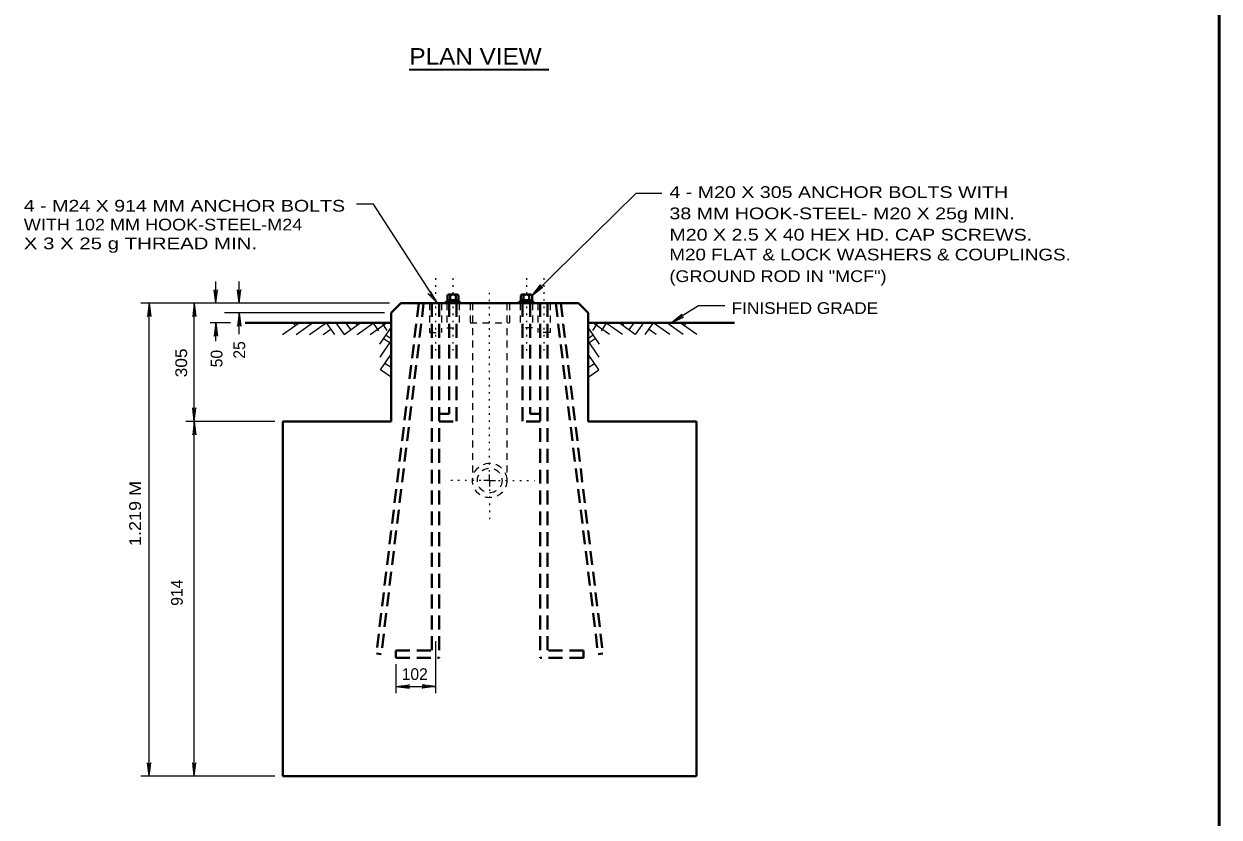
# Model space of a CAD drawing. Extents: x 312583 to 312854, y 144419 to 144597.
# Drawn here: x 312633.1 to 312710.6, y 144490.1 to 144541.5 of the extents above; entities that cross this region are included whole.
import ezdxf
from ezdxf.enums import TextEntityAlignment as Align

# ---------------------------------------------------------------- set-up
doc = ezdxf.new("R2010")
doc.units = 0
doc.header["$LTSCALE"] = 0.3
for name, pattern in [('DOTTED', [1.5, 0.3, -1.2]), ('MEDIUM_DASHED', [4.5, 3, -1.5]), ('SHORT_DASHED', [2.7, 1.5, -1.2])]:
    doc.linetypes.add(name, pattern=pattern)
doc.layers.add('1', color=7, linetype='Continuous', lineweight=40)
doc.layers.add('2', color=7, linetype='Continuous', lineweight=13)

msp = doc.modelspace()

# ---------------------------------------------------------------- linework, layer by layer
at = {"layer": '1', "lineweight": 53}
msp.add_line((312710.5662, 144423.0846), (312710.5662, 144585.0846), dxfattribs=at)
at = {"layer": '1', "linetype": 'DOTTED', "lineweight": 13}
for p, q in [((312659.772, 144525.0157), (312659.772, 144520.2087)), ((312660.9066, 144525.0157), (312660.9066, 144520.2087)), ((312665.6676, 144525.0157), (312665.6676, 144520.2087)), ((312666.8023, 144525.0157), (312666.8023, 144520.2087))]:
    msp.add_line(p, q, dxfattribs=at)
at = {"layer": '1'}
for p, q in [((312660.5463, 144523.4823), (312660.5463, 144523.8963)), ((312660.6383, 144523.9577), (312661.175, 144523.9577)), ((312660.7226, 144523.5973), (312660.7226, 144523.8963)), ((312661.083, 144523.5973), (312661.083, 144523.8963)), ((312661.267, 144523.4823), (312661.267, 144523.8963)), ((312665.3073, 144523.4823), (312665.3073, 144523.8963)), ((312665.3993, 144523.9577), (312665.936, 144523.9577)), ((312665.4836, 144523.5973), (312665.4836, 144523.8963)), ((312665.844, 144523.5973), (312665.844, 144523.8963)), ((312666.028, 144523.4823), (312666.028, 144523.8963)), ((312656.897, 144522.7617), (312657.5333, 144523.398)), ((312657.5333, 144523.398), (312669.0333, 144523.398)), ((312660.4236, 144523.4823), (312660.4236, 144523.398)), ((312660.4236, 144523.4823), (312661.382, 144523.4823)), ((312660.5463, 144523.5973), (312661.267, 144523.5973)), ((312661.382, 144523.4823), (312661.382, 144523.398)), ((312665.1846, 144523.4823), (312665.1846, 144523.398)), ((312665.1846, 144523.4823), (312666.143, 144523.4823)), ((312665.3073, 144523.5973), (312666.028, 144523.5973)), ((312666.143, 144523.4823), (312666.143, 144523.398)), ((312669.0333, 144523.398), (312669.6773, 144522.7617)), ((312647.444, 144522.1177), (312656.897, 144522.1177)), ((312656.897, 144522.7617), (312656.897, 144515.7313)), ((312669.6773, 144522.7617), (312669.6773, 144515.7313)), ((312669.6773, 144522.1177), (312679.161, 144522.1177)), ((312649.8666, 144515.7313), (312649.8666, 144492.7313)), ((312649.8666, 144515.7313), (312656.897, 144515.7313)), ((312669.6773, 144515.7313), (312676.7, 144515.7313)), ((312676.7, 144515.7313), (312676.7, 144492.7313)), ((312649.8666, 144492.7313), (312676.7, 144492.7313))]:
    msp.add_line(p, q, dxfattribs=at)
at = {"layer": '1', "linetype": 'MEDIUM_DASHED'}
for p, q in [((312658.6833, 144523.398), (312655.9386, 144500.674)), ((312659.0053, 144523.398), (312656.2606, 144500.6357)), ((312659.5343, 144523.398), (312659.5343, 144500.881)), ((312660.0096, 144523.398), (312660.0096, 144500.398)), ((312660.669, 144523.398), (312660.669, 144516.2143)), ((312661.1443, 144523.398), (312661.1443, 144515.7313)), ((312665.4223, 144523.398), (312665.4223, 144515.7313)), ((312665.9053, 144523.398), (312665.9053, 144516.2143)), ((312666.557, 144523.398), (312666.557, 144500.398)), ((312667.04, 144523.398), (312667.04, 144500.881)), ((312667.569, 144523.398), (312670.3136, 144500.6357)), ((312667.891, 144523.398), (312670.628, 144500.674)), ((312660.0096, 144516.2143), (312660.669, 144516.2143)), ((312666.557, 144516.2143), (312665.9053, 144516.2143)), ((312660.0096, 144515.7313), (312661.1443, 144515.7313)), ((312666.557, 144515.7313), (312665.4223, 144515.7313)), ((312656.2606, 144500.6357), (312655.9386, 144500.674)), ((312657.2113, 144500.881), (312659.5343, 144500.881)), ((312657.2113, 144500.881), (312657.2113, 144500.398)), ((312657.2113, 144500.398), (312660.0096, 144500.398)), ((312669.3553, 144500.398), (312666.5646, 144500.398)), ((312669.3553, 144500.881), (312667.04, 144500.881)), ((312669.3553, 144500.881), (312669.3553, 144500.398)), ((312670.3136, 144500.6357), (312670.628, 144500.674))]:
    msp.add_line(p, q, dxfattribs=at)
at = {"layer": '1', "linetype": 'SHORT_DASHED', "lineweight": 25}
for p, q in [((312659.3733, 144523.398), (312659.3733, 144521.4813)), ((312660.1706, 144523.398), (312660.1706, 144521.4813)), ((312660.508, 144523.398), (312660.508, 144521.8033)), ((312661.3053, 144523.398), (312661.3053, 144521.8033)), ((312662.164, 144523.398), (312662.164, 144511.898)), ((312664.4026, 144523.398), (312664.4026, 144511.898)), ((312664.5636, 144523.398), (312664.5636, 144522.1177)), ((312665.269, 144523.398), (312665.269, 144521.8033)), ((312666.0663, 144523.398), (312666.0663, 144521.8033)), ((312666.4036, 144523.398), (312666.4036, 144521.4813)), ((312667.201, 144523.398), (312667.201, 144521.4813)), ((312659.3733, 144521.4813), (312660.1706, 144521.4813)), ((312660.508, 144521.8033), (312661.3053, 144521.8033)), ((312666.0663, 144521.8033), (312665.269, 144521.8033)), ((312667.201, 144521.4813), (312666.4036, 144521.4813))]:
    msp.add_line(p, q, dxfattribs=at)
msp.add_lwpolyline([(312662.0106, 144523.398), (312662.0106, 144522.1177), (312664.5636, 144522.1177)], dxfattribs=at)
for radius in [1.1181, 0.7986]:
    msp.add_circle((312663.2852, 144511.8986), radius, dxfattribs=at)
at = {"layer": '1'}
for centre, radius, start, end in [((312660.6361, 144523.8597), 0.098, 23.18435, 156.81565), ((312660.9058, 144523.6563), 0.3014, 53.40512, 126.59488), ((312661.1751, 144523.8604), 0.0973, 22.90211, 157.09789), ((312665.3958, 144523.8597), 0.098, 23.18435, 156.81565), ((312665.6656, 144523.6563), 0.3014, 53.40512, 126.59488), ((312665.9348, 144523.8604), 0.0973, 22.90211, 157.09789)]:
    msp.add_arc(centre, radius, start, end, dxfattribs=at)
at = {"layer": '2', "lineweight": 35}
msp.add_line((312658.0673, 144538.5359), (312667.1094, 144538.5359), dxfattribs=at)
at = {"layer": '2'}
for p, q in [((312655.7623, 144529.815), (312654.6583, 144529.815)), ((312659.9023, 144523.398), (312655.7623, 144529.815)), ((312645.5426, 144523.398), (312645.5426, 144524.7933)), ((312647.0376, 144523.398), (312647.0376, 144524.7933)), ((312666.028, 144523.8963), (312666.5723, 144524.5787)), ((312666.028, 144523.8963), (312666.718, 144524.4253)), ((312666.5723, 144524.5787), (312666.4496, 144524.3027)), ((312666.718, 144524.4253), (312666.4496, 144524.3027)), ((312645.4353, 144524.2643), (312645.5426, 144523.9883)), ((312645.5426, 144523.398), (312645.4353, 144524.2643)), ((312645.65, 144524.2643), (312645.5426, 144523.9883)), ((312645.5426, 144523.398), (312645.65, 144524.2643)), ((312646.9303, 144524.2643), (312647.0376, 144523.9883)), ((312647.0376, 144523.398), (312646.9303, 144524.2643)), ((312647.145, 144524.2643), (312647.0376, 144523.9883)), ((312647.0376, 144523.398), (312647.145, 144524.2643)), ((312659.2813, 144524.019), (312659.5343, 144523.8657)), ((312659.9023, 144523.398), (312659.2813, 144524.019)), ((312659.45, 144524.1493), (312659.5343, 144523.8657)), ((312659.9023, 144523.398), (312659.45, 144524.1493)), ((312656.7973, 144523.398), (312640.6666, 144523.398)), ((312641.2186, 144523.398), (312641.1113, 144522.5317)), ((312641.2186, 144492.7313), (312641.2186, 144523.398)), ((312641.2186, 144523.398), (312641.326, 144522.5317)), ((312644.1396, 144523.398), (312644.0323, 144522.5317)), ((312644.1396, 144523.398), (312644.247, 144522.5317)), ((312641.1113, 144522.5317), (312641.2186, 144522.8077)), ((312641.326, 144522.5317), (312641.2186, 144522.8077)), ((312644.0323, 144522.5317), (312644.1396, 144522.8077)), ((312644.247, 144522.5317), (312644.1396, 144522.8077)), ((312646.4933, 144522.1177), (312645.1746, 144522.1177)), ((312645.5426, 144522.1177), (312645.4353, 144521.2513)), ((312645.5426, 144520.9217), (312645.5426, 144522.1177)), ((312645.5426, 144522.1177), (312645.65, 144521.2513)), ((312656.4753, 144522.7617), (312646.087, 144522.7617)), ((312647.0376, 144522.7617), (312646.9303, 144521.8953)), ((312646.9303, 144521.8953), (312647.0376, 144522.1713)), ((312647.0376, 144521.3893), (312647.0376, 144522.7617)), ((312647.0376, 144522.7617), (312647.145, 144521.8953)), ((312647.145, 144521.8953), (312647.0376, 144522.1713)), ((312649.859, 144521.3663), (312650.9246, 144522.1253)), ((312650.5566, 144522.1177), (312650.6716, 144521.949)), ((312650.7406, 144521.3663), (312651.8063, 144522.1253)), ((312651.6146, 144521.3663), (312652.688, 144522.1253)), ((312652.688, 144522.1253), (312653.2323, 144521.3663)), ((312653.3166, 144522.1253), (312653.8533, 144521.3587)), ((312653.8533, 144521.3587), (312654.942, 144522.133)), ((312653.9453, 144522.1253), (312654.275, 144521.6577)), ((312654.5663, 144522.1253), (312654.689, 144521.9567)), ((312654.689, 144521.3587), (312655.7316, 144522.1023)), ((312655.5323, 144521.3587), (312656.598, 144522.1177)), ((312655.7316, 144522.1023), (312656.069, 144521.604)), ((312656.2836, 144522.11), (312656.621, 144521.6193)), ((312670.283, 144522.11), (312669.9456, 144521.6193)), ((312671.042, 144521.3587), (312669.9686, 144522.1177)), ((312670.835, 144522.1023), (312670.5053, 144521.604)), ((312671.8853, 144521.3587), (312670.8426, 144522.1023)), ((312672.7133, 144521.3587), (312671.6246, 144522.133)), ((312672.0003, 144522.1253), (312671.8776, 144521.9567)), ((312672.629, 144522.1253), (312672.2993, 144521.6577)), ((312673.2576, 144522.1253), (312672.7133, 144521.3587)), ((312673.8863, 144522.1253), (312673.342, 144521.3663)), ((312674.952, 144521.3663), (312673.8863, 144522.1253)), ((312675.8336, 144521.3663), (312674.7603, 144522.1253)), ((312675.0593, 144522.1177), (312675.734, 144522.6697)), ((312675.0593, 144522.1177), (312675.849, 144522.4857)), ((312675.734, 144522.6697), (312675.5576, 144522.432)), ((312675.849, 144522.4857), (312675.5576, 144522.432)), ((312676.7153, 144521.3663), (312675.642, 144522.1253)), ((312676.0176, 144522.1177), (312675.895, 144521.949)), ((312645.4353, 144521.2513), (312645.5426, 144521.5273)), ((312645.65, 144521.2513), (312645.5426, 144521.5273)), ((312652.4963, 144521.3663), (312652.987, 144521.7113)), ((312656.161, 144520.7377), (312656.9046, 144521.8263)), ((312656.5826, 144521.3203), (312656.8893, 144521.1057)), ((312670.4056, 144520.7377), (312669.6696, 144521.8263)), ((312669.9916, 144521.3203), (312669.685, 144521.1057)), ((312674.0703, 144521.3663), (312673.5873, 144521.7113)), ((312656.184, 144519.8943), (312656.9046, 144520.9523)), ((312656.437, 144521.0903), (312656.897, 144520.7683)), ((312670.3903, 144519.8943), (312669.6696, 144520.9523)), ((312670.1296, 144521.0903), (312669.6773, 144520.7683)), ((312656.1993, 144519.0663), (312656.897, 144520.086)), ((312656.897, 144519.8253), (312656.7743, 144519.9097)), ((312670.3673, 144519.0663), (312669.6773, 144520.086)), ((312669.6773, 144519.8253), (312669.7923, 144519.9097)), ((312656.897, 144518.591), (312656.1993, 144519.0663)), ((312656.897, 144519.212), (312656.4906, 144519.488)), ((312669.6773, 144519.212), (312670.0836, 144519.488)), ((312669.6773, 144518.591), (312670.3673, 144519.0663)), ((312644.0323, 144516.5977), (312644.1396, 144516.3217)), ((312644.1396, 144515.7313), (312644.0323, 144516.5977)), ((312644.247, 144516.5977), (312644.1396, 144516.3217)), ((312644.1396, 144515.7313), (312644.247, 144516.5977)), ((312649.353, 144515.7313), (312643.5876, 144515.7313)), ((312644.1396, 144515.7313), (312644.0323, 144514.865)), ((312644.0323, 144514.865), (312644.1396, 144515.141)), ((312644.1396, 144515.7313), (312644.247, 144514.865)), ((312644.247, 144514.865), (312644.1396, 144515.141)), ((312663.2833, 144511.898), (312663.2833, 144512.2813)), ((312663.2833, 144511.898), (312662.9, 144511.898)), ((312663.2833, 144511.898), (312663.6666, 144511.898)), ((312663.2833, 144511.898), (312663.2833, 144511.5147)), ((312659.7643, 144501.4867), (312659.7643, 144498.121)), ((312657.2113, 144499.984), (312657.2113, 144498.121)), ((312657.2113, 144498.5427), (312658.0776, 144498.65)), ((312657.2113, 144498.5427), (312659.7643, 144498.5427)), ((312657.2113, 144498.5427), (312658.0776, 144498.4353)), ((312658.0776, 144498.65), (312657.8016, 144498.5427)), ((312658.0776, 144498.4353), (312657.8016, 144498.5427)), ((312658.898, 144498.65), (312659.174, 144498.5427)), ((312659.7643, 144498.5427), (312658.898, 144498.65)), ((312658.898, 144498.4353), (312659.174, 144498.5427)), ((312659.7643, 144498.5427), (312658.898, 144498.4353)), ((312641.1113, 144493.5977), (312641.2186, 144493.3217)), ((312641.2186, 144492.7313), (312641.1113, 144493.5977)), ((312641.326, 144493.5977), (312641.2186, 144493.3217)), ((312641.2186, 144492.7313), (312641.326, 144493.5977)), ((312644.0323, 144493.5977), (312644.1396, 144493.3217)), ((312644.1396, 144492.7313), (312644.0323, 144493.5977)), ((312644.247, 144493.5977), (312644.1396, 144493.3217)), ((312644.1396, 144492.7313), (312644.247, 144493.5977)), ((312649.353, 144492.7313), (312640.6666, 144492.7313))]:
    msp.add_line(p, q, dxfattribs=at)
at = {"layer": '2', "linetype": 'DOTTED'}
for p, q in [((312663.2833, 144512.473), (312663.2833, 144524.4023)), ((312662.7083, 144511.898), (312660.393, 144511.898)), ((312663.2833, 144511.323), (312663.2833, 144509.1227)), ((312663.8583, 144511.898), (312666.1966, 144511.898))]:
    msp.add_line(p, q, dxfattribs=at)
at = {"layer": '2'}
for points in [[(312666.028, 144523.8963), (312672.79, 144530.528), (312674.4536, 144530.528)], [(312644.1396, 144492.7313), (312644.1396, 144515.7313), (312644.1396, 144523.398)], [(312678.5246, 144523.214), (312676.815, 144523.214), (312675.0593, 144522.1177)]]:
    msp.add_lwpolyline(points, dxfattribs=at)

# ---------------------------------------------------------------- texts
at = {"layer": '2', "width": 1.1}
msp.add_text('PLAN VIEW', height=1.07, dxfattribs=at).set_placement((312662.3663, 144538.8577), align=Align.CENTER)
at = {"layer": '2'}
for s, width, p in [('4 - M20 X 305 ANCHOR BOLTS WITH', 1.25, (312674.9366, 144530.2127)), ('4 - M24 X 914 MM ANCHOR BOLTS ', 1.25, (312633.0872, 144529.3275)), ('38 MM HOOK-STEEL- M20 X 25g MIN.', 1.25, (312674.9366, 144528.8327)), ('WITH 102 MM HOOK-STEEL-M24 ', 1.15, (312633.0872, 144528.1075)), ('X 3 X 25 g THREAD MIN.', 1.3, (312633.0872, 144526.8875)), ('M20 X 2.5 X 40 HEX HD. CAP SCREWS.', 1.25, (312674.9366, 144527.4527)), ('M20 FLAT & LOCK WASHERS & COUPLINGS.', 1.2, (312674.929, 144526.1663)), ('(GROUND ROD IN "MCF")', 1.15, (312674.9366, 144524.7628)), ('FINISHED GRADE', 1.1, (312678.965, 144522.6941))]:
    msp.add_text(s, height=0.76, dxfattribs=dict(at, width=width)).set_placement(p)
for s, p in [('25', (312647.4313, 144519.7964)), ('50', (312645.96, 144519.2351)), ('914', (312643.3887, 144503.7764))]:
    msp.add_text(s, height=0.76, rotation=90, dxfattribs=at).set_placement(p)
for s, width, p in [('305', 1.1, (312643.669, 144518.5885)), ('1.219 M', 1.15, (312640.6778, 144507.6461))]:
    msp.add_text(s, height=0.76, rotation=90, dxfattribs=dict(at, width=width)).set_placement(p)
msp.add_text('102', height=0.76, dxfattribs=at).set_placement((312657.5803, 144498.965))

doc.saveas('drawing.dxf')
